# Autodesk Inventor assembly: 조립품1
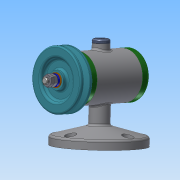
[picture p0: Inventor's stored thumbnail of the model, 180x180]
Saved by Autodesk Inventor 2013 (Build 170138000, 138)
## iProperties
Created: 2018-12
Part Number: 조립품1
Document SubType Name: Assembly
Designer: Administrator
Author: Administrator
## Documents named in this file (15)
- C:\Users\Administrator\Desktop\481207V1065\조립품1.iam
- C:\Users\Administrator\Desktop\481207V1065\본체.ipt
- C:\Users\Administrator\Desktop\481207V1065\뒤커버.ipt
- C:\Users\Administrator\Desktop\481207V1065\앞커버.ipt
- C:\Users\Administrator\Desktop\481207V1065\베어링 15 x 32 x 9.ipt
- C:\Users\Administrator\Desktop\481207V1065\오일 실 15 25 7.ipt
- C:\Users\Administrator\Desktop\481207V1065\축.ipt
- C:\Users\Administrator\Desktop\481207V1065\키 3 x 3 x 12.ipt
- C:\Users\Administrator\Desktop\481207V1065\볼트 M4 x 12.ipt
- C:\Users\Administrator\Desktop\481207V1065\V벨트풀리.ipt
- C:\Users\Administrator\Desktop\481207V1065\스프링와셔 8.ipt
- C:\Users\Administrator\Desktop\481207V1065\와셔 8x17.ipt
- C:\Users\Administrator\Desktop\481207V1065\너트 M8.ipt
- 너트 M8.ipt
- C:\Users\Administrator\Desktop\481207V1065\고무캡.ipt
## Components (2 placed, 2 different names)
1. V벨트풀리:1
2. 고무캡:1
